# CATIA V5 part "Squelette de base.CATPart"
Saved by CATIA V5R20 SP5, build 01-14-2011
Part number: Squelette de base
Publications: "A", "B", "C", "D", "F", "E", "I"
Bounding box of the stored display mesh (mm): x 0 to 0, y 0 to 618.933, z -900 to 128.204
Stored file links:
  J:\Thinkmotion\Projet IAO\A envoyer\Squelette de base.CATPart
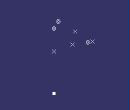
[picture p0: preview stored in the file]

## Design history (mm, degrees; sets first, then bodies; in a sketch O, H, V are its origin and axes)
Point1 "C": (0, 300, 246), relative to Point4
Point2 "D": type Between, FirstPoint Point1, SecondPoint Point6, Ratio 0.75, Support yz-plane
Set1
  Point3 "A": (0, 0, 0)
  Point4 "B": (0, 0, -320), relative to Point3
  Point5 "F": type OnPlane, Support yz-plane, H 68.933, V 128.204, Direction (0, 1, 0)
  Point6 "E": type OnPlane, Support yz-plane, RefPoint Point5, H 550, V 0, Direction (0, 1, 0)
  Point7 "I": (0, 0, -900), relative to Point3
  Point8 "V": type Between, FirstPoint Point5, SecondPoint Point6, Ratio 0.5
Body1 (main body)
